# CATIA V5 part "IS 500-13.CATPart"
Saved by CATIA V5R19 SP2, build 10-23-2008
Part number: IS 500-13
Bounding box of the stored display mesh (mm): x -22.494 to 22.494, y -22.494 to 22.494, z 0 to 110.4
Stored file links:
  C:\Users\Bora\Desktop\3D Katı model\IS serisi\IS 500\IS 500-13.CATPart
  C:\Program Files\Dassault Systemes\B19\intel_a\reffiles\standard\MetricThickPitch.txt
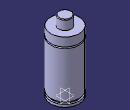
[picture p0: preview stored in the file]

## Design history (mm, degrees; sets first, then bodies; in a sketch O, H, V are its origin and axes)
Body1 (main body)
  Sketch1 on yz-plane, origin (0, 0, 0), H (0, 1, 0), V (0, 0, 1)
    point P3 (10, 109.4)
    point P5 (10, 109.4)
    point P7 (22.5, 81.9)
    point P8 (22.5, 79.9)
    point P12 (22.5, 79.9)
    point P13 (22.5, 81.9)
    line L1 (22.5, 0) -> (22.5, 4)
    line L2 (10, 109.4) -> (10, 95.4)
    arc A1 centre (9, 109.4) radius 1 from (10, 109.4) to (9, 110.4) ccw
    arc A2 centre (22.5, 80.9) radius 1 from (22.5, 81.9) to (22.5, 79.9) ccw
    line L3 (20, 7.5) -> (20, 4)
    line L4 (22.5, 7.5) -> (22.5, 79.9)
    line L5 (22.5, 81.9) -> (22.5, 95.4)
    line L6 (9, 110.4) -> (0, 110.4)
    line L7 (10, 95.4) -> (22.5, 95.4)
    line L8 (20, 7.5) -> (22.5, 7.5)
    line L9 (20, 4) -> (22.5, 4)
    line L10 (0, 0) -> (22.5, 0)
    tangency: L6 A1
    horizontal: L7 H, L8 H, L9 H, L10 H
    coincidence: P3 P5, P7 P13, P8 P12
  Shaft1: profile Sketch1, axis Sketch1.V, angle 360
  Sketch2 on face of Shaft1 from Sketch1.L10, origin (0, 0, 0), H (1, 0, 0), V (0, -1, 0)
    point P1 (10, 0)
    distance P1 V = 10
  Hole1: placed by Sketch2, at (10, 0, 0) direction (0, 0, 1), diameter 6.647, depth 13, threaded "M8", thread diameter 8, thread depth 13, pitch 1.25
  Sketch3 on face of Shaft1 from Sketch1.L10, origin (0, 0, 0), H (1, 0, 0), V (0, -1, 0)
    point P1 (-10, 0)
    distance P1 V = 10
  Hole2: placed by Sketch3, at (-10, 0, 0) direction (0, 0, 1), diameter 6.647, depth 13, threaded "M8", thread diameter 8, thread depth 13, pitch 1.25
